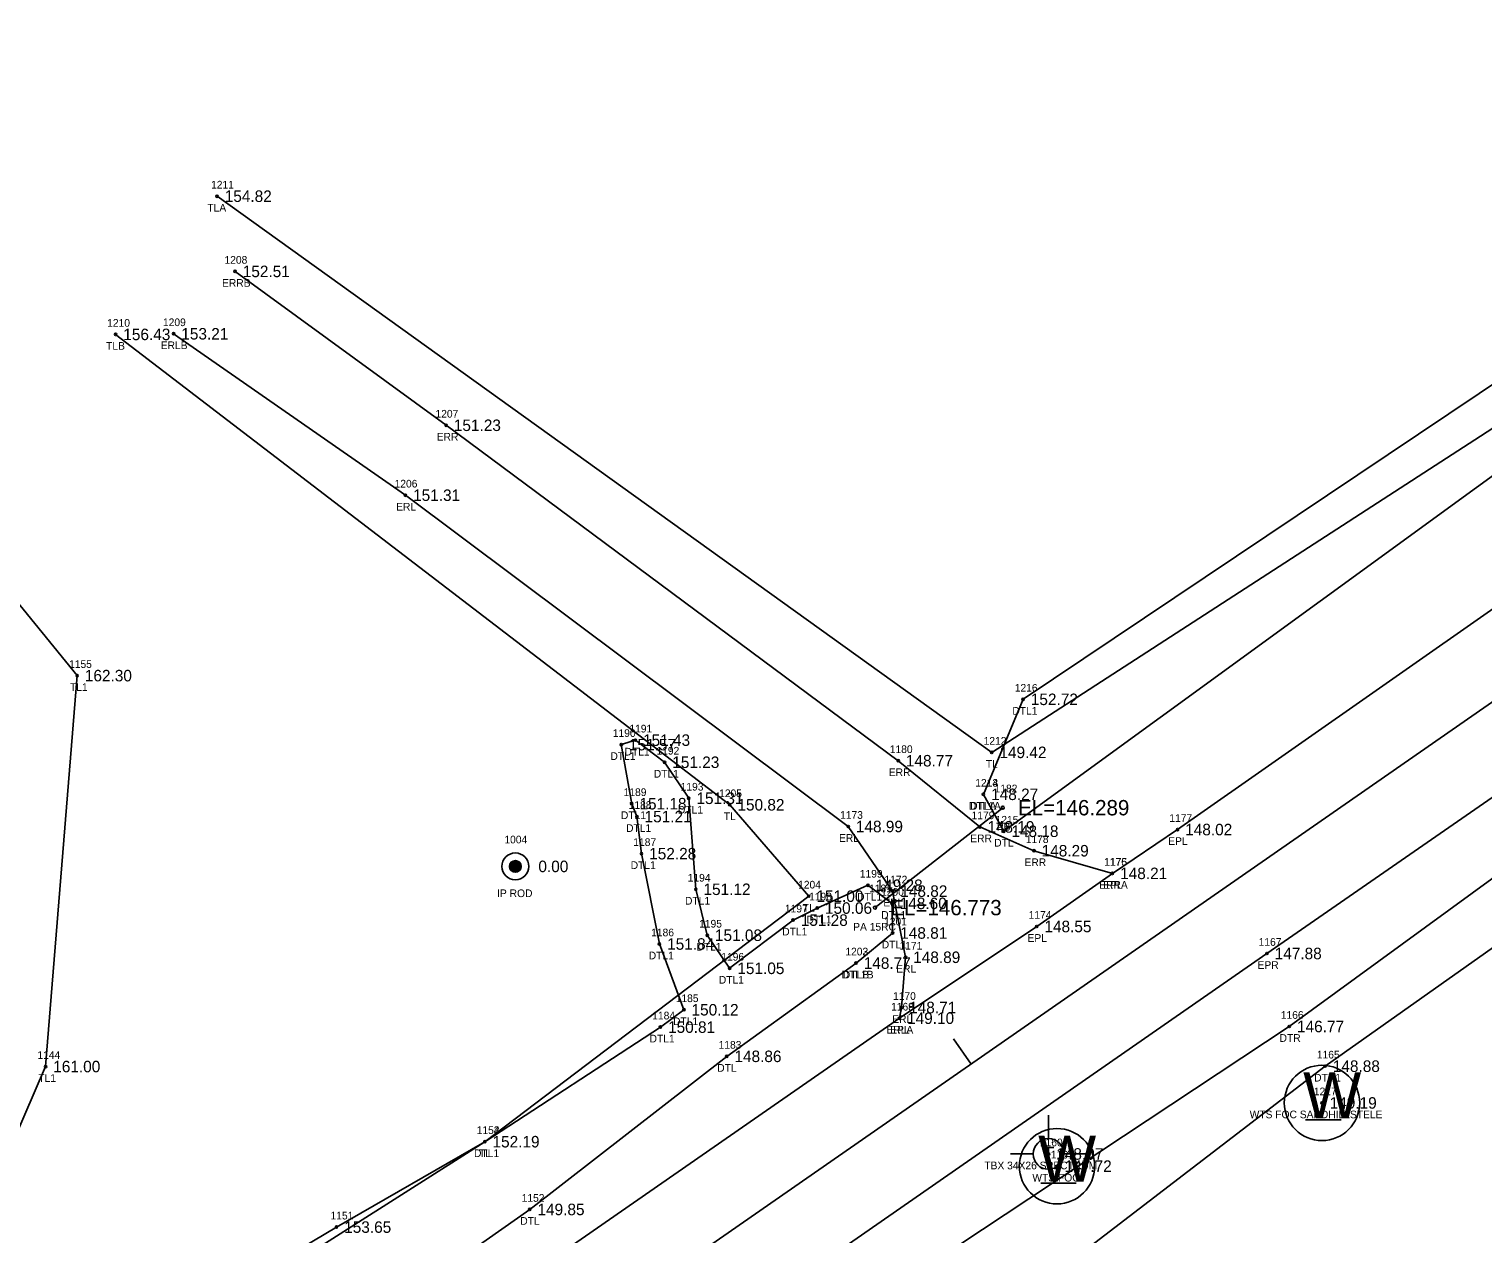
# Model space of a CAD drawing. Extents: x 2449052 to 2452984, y 1012343 to 1015262.
# Drawn here: x 2450486.8 to 2450676.2, y 1013609.6 to 1013766.6 of the extents above; entities that cross this region are included whole.
import ezdxf

# ---------------------------------------------------------------- set-up
doc = ezdxf.new("R2010")
doc.units = 0
for name, color, linetype in [('RD_EX_DR_Pipe', 7, 'Continuous'), ('RD_EX_DR_Pipe_txCode', 7, 'Continuous'), ('RD_EX_DV_Prop_txCode', 7, 'Continuous'), ('RD_EX_DV_PropPin', 7, 'Continuous'), ('RD_EX_H2O', 7, 'Continuous'), ('RD_EX_H2O_txCode', 7, 'Continuous'), ('RD_EX_Road', 7, 'Continuous'), ('RD_EX_Road_txCode', 7, 'Continuous'), ('RD_EX_TX_DV_Prop_ELEV', 7, 'Continuous'), ('RD_EX_TX_H2O_ELEV', 7, 'Continuous'), ('RD_EX_TX_Road_ELEV', 7, 'Continuous'), ('RD_EX_TX_UT_ELEV', 7, 'Continuous'), ('RD_EX_TX_VEG_ELEV', 7, 'Continuous'), ('RD_EX_UT', 7, 'Continuous'), ('RD_EX_UT_txCode', 7, 'Continuous'), ('RD_EX_VEG', 7, 'Continuous'), ('RD_EX_VEG_txCode', 7, 'Continuous'), ('RD_HC_Cl', 7, 'Continuous'), ('RD_HC_Data_Tic', 7, 'Continuous'), ('RD_SMD_Locator', 7, 'Continuous'), ('RD_TX_Pipe_ElevEX', 7, 'Continuous')]:
    doc.layers.add(name, color=color, linetype=linetype)

msp = doc.modelspace()

# ---------------------------------------------------------------- linework, layer by layer
at = {"layer": 'RD_EX_DR_Pipe'}
msp.add_line((2450597.01, 1013652.11), (2450613.65, 1013665.13), dxfattribs=at)
at = {"layer": 'RD_EX_DV_PropPin'}
for p, q in [((2450549.39, 1013657.29), (2450549.39, 1013657.68)), ((2450549.43, 1013657.19), (2450549.43, 1013657.78)), ((2450549.46, 1013657.11), (2450549.46, 1013657.85)), ((2450549.5, 1013657.06), (2450549.5, 1013657.91)), ((2450549.53, 1013657.01), (2450549.53, 1013657.96)), ((2450549.57, 1013656.97), (2450549.57, 1013658)), ((2450549.6, 1013656.93), (2450549.6, 1013658.03)), ((2450549.64, 1013656.9), (2450549.64, 1013658.07)), ((2450549.67, 1013656.87), (2450549.67, 1013658.09)), ((2450549.71, 1013656.85), (2450549.71, 1013658.12)), ((2450549.74, 1013656.83), (2450549.74, 1013658.14)), ((2450549.78, 1013656.81), (2450549.78, 1013658.16)), ((2450549.81, 1013656.79), (2450549.81, 1013658.18)), ((2450549.85, 1013656.78), (2450549.85, 1013658.19)), ((2450549.88, 1013656.76), (2450549.88, 1013658.2)), ((2450549.92, 1013656.75), (2450549.92, 1013658.22)), ((2450549.95, 1013656.74), (2450549.95, 1013658.22)), ((2450549.99, 1013656.74), (2450549.99, 1013658.23)), ((2450550.02, 1013656.73), (2450550.02, 1013658.24)), ((2450550.06, 1013656.73), (2450550.06, 1013658.24)), ((2450550.09, 1013656.72), (2450550.09, 1013658.24)), ((2450550.13, 1013656.72), (2450550.13, 1013658.25)), ((2450550.16, 1013656.72), (2450550.16, 1013658.24)), ((2450550.2, 1013656.73), (2450550.2, 1013658.24)), ((2450550.23, 1013656.73), (2450550.23, 1013658.24)), ((2450550.27, 1013656.74), (2450550.27, 1013658.23)), ((2450550.3, 1013656.74), (2450550.3, 1013658.22)), ((2450550.34, 1013656.75), (2450550.34, 1013658.22)), ((2450550.37, 1013656.76), (2450550.37, 1013658.2)), ((2450550.41, 1013656.78), (2450550.41, 1013658.19)), ((2450550.44, 1013656.79), (2450550.44, 1013658.18)), ((2450550.48, 1013656.81), (2450550.48, 1013658.16)), ((2450550.51, 1013656.83), (2450550.51, 1013658.14)), ((2450550.55, 1013656.85), (2450550.55, 1013658.12)), ((2450550.58, 1013656.87), (2450550.58, 1013658.09)), ((2450550.62, 1013656.9), (2450550.62, 1013658.07)), ((2450550.65, 1013656.93), (2450550.65, 1013658.03)), ((2450550.69, 1013656.97), (2450550.69, 1013658)), ((2450550.72, 1013657.01), (2450550.72, 1013657.96)), ((2450550.76, 1013657.06), (2450550.76, 1013657.91)), ((2450550.79, 1013657.11), (2450550.79, 1013657.85)), ((2450550.83, 1013657.19), (2450550.83, 1013657.78)), ((2450550.86, 1013657.29), (2450550.86, 1013657.68))]:
    msp.add_line(p, q, dxfattribs=at)
for radius in [1.75, 0.761]:
    msp.add_circle((2450550.13, 1013657.48), radius, dxfattribs=at)
at = {"layer": 'RD_EX_H2O'}
for points in [[(2450611.14, 1013666.87), (2450616.31, 1013679.25), (2450719.37, 1013748.33), (2450722.94, 1013749.68), (2450728.13, 1013757.45), (2450733.94, 1013756.08)], [(2450611.14, 1013666.87), (2450613.78, 1013662.06), (2450716.62, 1013736.81), (2450727.45, 1013740.5), (2450727.63, 1013739.78), (2450734.85, 1013745.44), (2450737.25, 1013753.64), (2450733.94, 1013756.08)], [(2450167.46, 1013291.72), (2450167.1, 1013295.75), (2450175.19, 1013302.21), (2450253.51, 1013357.72), (2450334.87, 1013415.7), (2450415.19, 1013473.64), (2450493.27, 1013528.65), (2450573.99, 1013585.66), (2450651, 1013636.62), (2450748.48, 1013707.64), (2450786.48, 1013731.51)], [(2450167.46, 1013291.72), (2450171.71, 1013290.19), (2450180.8, 1013296.66), (2450259.89, 1013349.14), (2450344.33, 1013402.02), (2450412.23, 1013445.13), (2450424.15, 1013461.12), (2450474.5, 1013497.19), (2450500.92, 1013517.59), (2450581.65, 1013574.66), (2450655.67, 1013631.45), (2450753.63, 1013700.7), (2450792.21, 1013722.47), (2450790.93, 1013725.57), (2450786.48, 1013731.51)], [(2450519.01, 1013605.81), (2450526.82, 1013610.48), (2450546.15, 1013621.61), (2450569.03, 1013636.54), (2450572.09, 1013638.8), (2450568.91, 1013647.37), (2450566.57, 1013659.14), (2450565.97, 1013663.97), (2450565.3, 1013665.65), (2450563.93, 1013673.35), (2450565.77, 1013673.93), (2450569.58, 1013671.05), (2450572.73, 1013666.36), (2450573.65, 1013654.5), (2450575.14, 1013648.51), (2450578.06, 1013644.2), (2450586.32, 1013650.48), (2450589.48, 1013652.05), (2450596.08, 1013655.02), (2450599.22, 1013652.66), (2450599.29, 1013648.8), (2450594.53, 1013644.88)], [(2450082.81, 1013302.86), (2450086.85, 1013297.03), (2450148.02, 1013337.87), (2450230.55, 1013392.65), (2450311.52, 1013448.88), (2450394.54, 1013504.43), (2450473.16, 1013557.42), (2450552.01, 1013612.78), (2450577.68, 1013632.73), (2450594.53, 1013644.88)]]:
    msp.add_lwpolyline(points, dxfattribs=at)
at = {"layer": 'RD_EX_Road'}
for points in [[(2449674.89, 1012994.69), (2449752.35, 1013048.28), (2449834.92, 1013105.96), (2449914.72, 1013161.11), (2449995.66, 1013217.59), (2450075.29, 1013272.9), (2450081.34, 1013277.24), (2450093.41, 1013285.64), (2450155.49, 1013328.69), (2450236.05, 1013384.7), (2450317.88, 1013441.24), (2450398.87, 1013497.28), (2450477.09, 1013551.76), (2450555.6, 1013606.73), (2450600.18, 1013637.7), (2450618.08, 1013649.65), (2450627.95, 1013656.57), (2450636.43, 1013662.28), (2450733.79, 1013730.39), (2450811.43, 1013784.18), (2450891.39, 1013839.9), (2450907.04, 1013850.14)], [(2449685.94, 1012977.62), (2449764.81, 1013032.3), (2449846, 1013088.39), (2449925.85, 1013144.07), (2450006.8, 1013200.56), (2450086.45, 1013256.14), (2450125.67, 1013283.43), (2450163.55, 1013309.93), (2450166.36, 1013312.09), (2450247.44, 1013367.98), (2450329.19, 1013424.41), (2450410.32, 1013481.09), (2450488.38, 1013535.38), (2450567.5, 1013590.14), (2450648.09, 1013646.13), (2450745.08, 1013713.3), (2450823, 1013767.39), (2450902.19, 1013823.2), (2450918.14, 1013833.95)], [(2450627.95, 1013656.57), (2450617.72, 1013659.52), (2450610.65, 1013662.63), (2450600.03, 1013671.25), (2450541.11, 1013714.96), (2450513.6, 1013735.01)], [(2450600.18, 1013637.7), (2450600.45, 1013639.09), (2450600.98, 1013645.64), (2450599.3, 1013654.26), (2450593.51, 1013662.68), (2450535.8, 1013705.85), (2450505.59, 1013726.88)]]:
    msp.add_lwpolyline(points, dxfattribs=at)
at = {"layer": 'RD_EX_UT'}
for p, q in [((2450619.62, 1013625.07), (2450619.62, 1013622.01)), ((2450653.13, 1013624.45), (2450657.76, 1013624.45)), ((2450614.68, 1013620.02), (2450617.62, 1013620.02)), ((2450621.62, 1013620.02), (2450624.68, 1013620.02)), ((2450618.6, 1013616.21), (2450623.23, 1013616.21))]:
    msp.add_line(p, q, dxfattribs=at)
for centre, radius in [((2450655.26, 1013626.66), 4.91), ((2450620.72, 1013618.41), 4.91), ((2450619.62, 1013620.01), 2)]:
    msp.add_circle(centre, radius, dxfattribs=at)
at = {"layer": 'RD_EX_VEG'}
for points in [[(2450511.25, 1013744.81), (2450612.22, 1013672.34), (2450883.9, 1013848.07), (2451091.43, 1014003.45), (2451271.45, 1014121.26), (2451583.45, 1014347.48), (2451819.08, 1014511.44), (2452219.54, 1014796.6), (2452332.78, 1014867.52)], [(2450316.02, 1013471.19), (2450479.16, 1013608.91), (2450488.9, 1013631.4), (2450493.02, 1013682.34), (2450465.78, 1013715.74), (2450452.26, 1013733.28)], [(2450316.02, 1013471.19), (2450462.83, 1013574.31), (2450498.07, 1013591.03), (2450546.15, 1013621.61), (2450588.36, 1013653.6), (2450578.07, 1013665.51), (2450498.03, 1013726.8)]]:
    msp.add_lwpolyline(points, dxfattribs=at)
at = {"layer": 'RD_HC_Cl'}
msp.add_line((2449680.91, 1012986.23), (2452350.19, 1014841.68), dxfattribs=at)
at = {"layer": 'RD_HC_Data_Tic'}
msp.add_line((2450609.53, 1013631.72), (2450607.24, 1013635.01), dxfattribs=at)
at = {"layer": 'RD_SMD_Locator'}
for centre, radius in [((2450511.25, 1013744.81), 0.15), ((2450513.6, 1013735.01), 0.15), ((2450505.59, 1013726.88), 0.15), ((2450498.03, 1013726.8), 0.15), ((2450541.11, 1013714.96), 0.15), ((2450535.8, 1013705.85), 0.15), ((2450493.02, 1013682.34), 0.15), ((2450616.31, 1013679.25), 0.15), ((2450565.77, 1013673.93), 0.15), ((2450563.93, 1013673.35), 0.15), ((2450612.22, 1013672.34), 0.15), ((2450569.58, 1013671.05), 0.15), ((2450600.03, 1013671.25), 0.15), ((2450572.73, 1013666.36), 0.15), ((2450611.14, 1013666.87), 0.15), ((2450611.14, 1013666.87), 0.15), ((2450565.3, 1013665.65), 0.15), ((2450578.07, 1013665.51), 0.15), ((2450613.65, 1013665.13), 0.2), ((2450565.97, 1013663.97), 0.15), ((2450593.51, 1013662.68), 0.15), ((2450610.65, 1013662.63), 0.15), ((2450613.78, 1013662.06), 0.15), ((2450636.43, 1013662.28), 0.15), ((2450566.57, 1013659.14), 0.15), ((2450617.72, 1013659.52), 0.15), ((2450550.13, 1013657.48), 0.15), ((2450596.08, 1013655.02), 0.15), ((2450627.95, 1013656.57), 0.15), ((2450627.95, 1013656.57), 0.15), ((2450573.65, 1013654.5), 0.15), ((2450588.36, 1013653.6), 0.15), ((2450599.3, 1013654.26), 0.15), ((2450589.48, 1013652.05), 0.15), ((2450597.01, 1013652.11), 0.2), ((2450599.22, 1013652.66), 0.15), ((2450586.32, 1013650.48), 0.15), ((2450618.08, 1013649.65), 0.15), ((2450568.91, 1013647.37), 0.15), ((2450575.14, 1013648.51), 0.15), ((2450599.29, 1013648.8), 0.15), ((2450600.98, 1013645.64), 0.15), ((2450648.09, 1013646.13), 0.15), ((2450578.06, 1013644.2), 0.15), ((2450594.53, 1013644.88), 0.15), ((2450594.53, 1013644.88), 0.15), ((2450572.09, 1013638.8), 0.15), ((2450600.45, 1013639.09), 0.15), ((2450569.03, 1013636.54), 0.15), ((2450600.18, 1013637.7), 0.15), ((2450600.18, 1013637.7), 0.15), ((2450651, 1013636.62), 0.15), ((2450577.68, 1013632.73), 0.15), ((2450488.9, 1013631.4), 0.15), ((2450655.67, 1013631.45), 0.15), ((2450655.26, 1013626.66), 0.15), ((2450546.15, 1013621.61), 0.15), ((2450546.15, 1013621.61), 0.15), ((2450619.62, 1013620.01), 0.15), ((2450620.72, 1013618.41), 0.15), ((2450552.01, 1013612.78), 0.15), ((2450526.82, 1013610.48), 0.15)]:
    msp.add_circle(centre, radius, dxfattribs=at)

# ---------------------------------------------------------------- texts
at = {"layer": 'RD_EX_DR_Pipe_txCode'}
for s, p in [('1182', (2450612.59, 1013667.13)), ('PB', (2450612.87, 1013662.13)), ('1181', (2450596.23, 1013654.11)), ('PA 15RC', (2450594.16, 1013649.11))]:
    msp.add_text(s, height=1, dxfattribs=at).set_placement(p)
at = {"layer": 'RD_EX_DV_Prop_txCode'}
for s, p in [('1004', (2450548.7, 1013660.48)), ('IP ROD', (2450547.75, 1013653.48))]:
    msp.add_text(s, height=1, dxfattribs=at).set_placement(p)
at = {"layer": 'RD_EX_H2O_txCode'}
for s, p in [('1216', (2450615.22, 1013680.25)), ('DTL1', (2450614.9, 1013677.25)), ('1191', (2450564.99, 1013674.93)), ('1190', (2450562.83, 1013674.35)), ('DTL1', (2450562.52, 1013671.35)), ('DTL1', (2450564.36, 1013671.93)), ('1192', (2450568.52, 1013672.05)), ('DTL1', (2450568.17, 1013669.05)), ('1193', (2450571.67, 1013667.36)), ('1213', (2450610.07, 1013667.87)), ('1214', (2450610.07, 1013667.87)), ('1189', (2450564.24, 1013666.65)), ('DTL1', (2450563.89, 1013663.65)), ('1188', (2450564.9, 1013664.97)), ('DTL1', (2450571.32, 1013664.36)), ('DTL1A', (2450609.24, 1013664.87)), ('DTLA', (2450609.41, 1013664.87)), ('DTL1', (2450564.56, 1013661.97)), ('1215', (2450612.72, 1013663.06)), ('1187', (2450565.5, 1013660.14)), ('DTL', (2450612.54, 1013660.06)), ('DTL1', (2450565.16, 1013657.14)), ('1199', (2450595.02, 1013656.02)), ('1194', (2450572.59, 1013655.5)), ('DTL1', (2450572.24, 1013652.5)), ('1198', (2450588.41, 1013653.05)), ('DTL1', (2450594.67, 1013653.02)), ('1200', (2450597.79, 1013653.66)), ('1197', (2450585.26, 1013651.48)), ('DTL1', (2450597.81, 1013650.66)), ('1186', (2450567.83, 1013648.37)), ('1195', (2450574.08, 1013649.51)), ('DTL1', (2450584.91, 1013648.48)), ('DTL1', (2450588.07, 1013650.05)), ('1201', (2450598.19, 1013649.8)), ('DTL1', (2450573.73, 1013646.51)), ('DTL1', (2450597.88, 1013646.8)), ('DTL1', (2450567.51, 1013645.37)), ('1196', (2450576.97, 1013645.2)), ('1202', (2450593.14, 1013645.88)), ('1203', (2450593.14, 1013645.88)), ('DTL1B', (2450592.65, 1013642.88)), ('DTLB', (2450592.81, 1013642.88)), ('DTL1', (2450576.65, 1013642.2)), ('1185', (2450571.03, 1013639.8)), ('1184', (2450567.97, 1013637.54)), ('1166', (2450649.89, 1013637.62)), ('DTL1', (2450570.68, 1013636.8)), ('DTL1', (2450567.62, 1013634.54)), ('1183', (2450576.62, 1013633.73)), ('DTR', (2450649.73, 1013634.62)), ('1165', (2450654.59, 1013632.45)), ('DTL', (2450576.44, 1013630.73)), ('DTR1', (2450654.24, 1013629.45)), ('1153', (2450545.09, 1013622.61)), ('DTL1', (2450544.74, 1013619.61)), ('1152', (2450550.95, 1013613.78)), ('1151', (2450526.04, 1013611.48)), ('DTL', (2450550.77, 1013610.78))]:
    msp.add_text(s, height=1, dxfattribs=at).set_placement(p)
at = {"layer": 'RD_EX_Road_txCode'}
for s, p in [('1208', (2450512.22, 1013736.01)), ('ERRB', (2450511.9, 1013733.01)), ('1209', (2450504.2, 1013727.88)), ('ERLB', (2450503.91, 1013724.88)), ('1207', (2450539.72, 1013715.96)), ('ERR', (2450539.88, 1013712.96)), ('1206', (2450534.39, 1013706.85)), ('ERL', (2450534.59, 1013703.85)), ('1180', (2450598.93, 1013672.25)), ('ERR', (2450598.8, 1013669.25)), ('1173', (2450592.45, 1013663.68)), ('1179', (2450609.59, 1013663.63)), ('1177', (2450635.36, 1013663.28)), ('ERL', (2450592.31, 1013660.68)), ('ERR', (2450609.42, 1013660.63)), ('1178', (2450616.65, 1013660.52)), ('EPL', (2450635.22, 1013660.28)), ('ERR', (2450616.49, 1013657.52)), ('1176', (2450626.86, 1013657.57)), ('1175', (2450626.89, 1013657.57)), ('1172', (2450598.24, 1013655.26)), ('ERRA', (2450626.23, 1013654.57)), ('EPL', (2450626.74, 1013654.57)), ('ERL', (2450598.09, 1013652.26)), ('1174', (2450617.02, 1013650.65)), ('1171', (2450600.2, 1013646.64)), ('EPL', (2450616.88, 1013647.65)), ('1167', (2450647, 1013647.13)), ('ERL', (2450599.77, 1013643.64)), ('EPR', (2450646.86, 1013644.13)), ('1170', (2450599.35, 1013640.09)), ('1168', (2450599.1, 1013638.7)), ('1169', (2450599.1, 1013638.7)), ('ERL', (2450599.25, 1013637.09)), ('ERLA', (2450598.49, 1013635.7)), ('EPL', (2450598.98, 1013635.7))]:
    msp.add_text(s, height=1, dxfattribs=at).set_placement(p)
at = {"layer": 'RD_EX_TX_DV_Prop_ELEV'}
msp.add_text('0.00', height=1.5, dxfattribs=at).set_placement((2450553.13, 1013656.73))
at = {"layer": 'RD_EX_TX_H2O_ELEV'}
for s, p in [('152.72', (2450617.31, 1013678.5)), ('151.57', (2450564.93, 1013672.6)), ('151.43', (2450566.77, 1013673.18)), ('151.23', (2450570.58, 1013670.3)), ('151.18', (2450566.3, 1013664.9)), ('151.31', (2450573.73, 1013665.61)), ('148.27', (2450612.14, 1013666.12)), ('148.27', (2450612.14, 1013666.12)), ('151.21', (2450566.97, 1013663.22)), ('148.18', (2450614.78, 1013661.31)), ('152.28', (2450567.57, 1013658.39)), ('151.12', (2450574.65, 1013653.75)), ('149.28', (2450597.08, 1013654.27)), ('148.60', (2450600.22, 1013651.91)), ('151.28', (2450587.32, 1013649.73)), ('150.06', (2450590.48, 1013651.3)), ('148.81', (2450600.29, 1013648.05)), ('151.84', (2450569.91, 1013646.62)), ('151.08', (2450576.14, 1013647.76)), ('148.77', (2450595.53, 1013644.13)), ('148.77', (2450595.53, 1013644.13)), ('151.05', (2450579.06, 1013643.45)), ('150.12', (2450573.09, 1013638.05)), ('150.81', (2450570.03, 1013635.79)), ('146.77', (2450652, 1013635.87)), ('148.86', (2450578.68, 1013631.98)), ('148.88', (2450656.67, 1013630.7)), ('152.19', (2450547.15, 1013620.86)), ('149.85', (2450553.01, 1013612.03)), ('153.65', (2450527.82, 1013609.73))]:
    msp.add_text(s, height=1.5, dxfattribs=at).set_placement(p)
at = {"layer": 'RD_EX_TX_Road_ELEV'}
for s, p in [('152.51', (2450514.6, 1013734.26)), ('153.21', (2450506.59, 1013726.13)), ('151.23', (2450542.11, 1013714.21)), ('151.31', (2450536.8, 1013705.1)), ('148.77', (2450601.03, 1013670.5)), ('148.99', (2450594.51, 1013661.93)), ('148.19', (2450611.65, 1013661.88)), ('148.02', (2450637.43, 1013661.53)), ('148.29', (2450618.72, 1013658.77)), ('148.21', (2450628.95, 1013655.82)), ('148.21', (2450628.95, 1013655.82)), ('148.82', (2450600.3, 1013653.51)), ('148.55', (2450619.08, 1013648.9)), ('148.89', (2450601.98, 1013644.89)), ('147.88', (2450649.09, 1013645.38)), ('148.71', (2450601.45, 1013638.34)), ('149.10', (2450601.18, 1013636.95)), ('149.10', (2450601.18, 1013636.95))]:
    msp.add_text(s, height=1.5, dxfattribs=at).set_placement(p)
at = {"layer": 'RD_EX_TX_UT_ELEV'}
for s, p in [('149.19', (2450656.26, 1013625.91)), ('148.07', (2450620.62, 1013619.26)), ('147.72', (2450621.72, 1013617.67))]:
    msp.add_text(s, height=1.5, dxfattribs=at).set_placement(p)
at = {"layer": 'RD_EX_TX_VEG_ELEV'}
for s, p in [('154.82', (2450512.25, 1013744.06)), ('156.43', (2450499.03, 1013726.05)), ('162.30', (2450494.02, 1013681.59)), ('149.42', (2450613.22, 1013671.59)), ('150.82', (2450579.07, 1013664.76)), ('151.00', (2450589.36, 1013652.85)), ('161.00', (2450489.9, 1013630.65)), ('152.19', (2450547.15, 1013620.86))]:
    msp.add_text(s, height=1.5, dxfattribs=at).set_placement(p)
at = {"layer": 'RD_EX_UT'}
for s, height, p in [('W', 6, (2450652.8, 1013624.66)), ('W', 6, (2450618.26, 1013616.41)), ('T', 2, (2450618.77, 1013618.96))]:
    msp.add_text(s, height=height, dxfattribs=at).set_placement(p)
at = {"layer": 'RD_EX_UT_txCode'}
for s, p in [('1217', (2450654.2, 1013627.66)), ('WTS FOC SANDHILLSTELE', (2450645.83, 1013624.66)), ('1160', (2450618.49, 1013621.01)), ('TBX 34X26 SPECTRUM', (2450611.25, 1013618.01)), ('1161', (2450619.92, 1013619.42)), ('WTS FOC', (2450617.51, 1013616.42))]:
    msp.add_text(s, height=1, dxfattribs=at).set_placement(p)
at = {"layer": 'RD_EX_VEG_txCode'}
for s, p in [('1211', (2450510.47, 1013745.81)), ('TLA', (2450509.99, 1013742.81)), ('1210', (2450496.93, 1013727.8)), ('TLB', (2450496.79, 1013724.8)), ('1155', (2450491.96, 1013683.34)), ('TL1', (2450492.08, 1013680.34)), ('1212', (2450611.16, 1013673.34)), ('TL', (2450611.45, 1013670.34)), ('1205', (2450576.69, 1013666.51)), ('TL', (2450577.3, 1013663.51)), ('1204', (2450586.98, 1013654.6)), ('TL', (2450587.59, 1013651.6)), ('1144', (2450487.84, 1013632.4)), ('TL1', (2450487.96, 1013629.4)), ('1154', (2450545.09, 1013622.61)), ('TL', (2450545.38, 1013619.61))]:
    msp.add_text(s, height=1, dxfattribs=at).set_placement(p)
at = {"layer": 'RD_TX_Pipe_ElevEX'}
for s, p in [('EL=146.289', (2450615.65, 1013664.13)), ('EL=146.773', (2450599.01, 1013651.11))]:
    msp.add_text(s, height=2, dxfattribs=at).set_placement(p)

doc.saveas('drawing.dxf')
